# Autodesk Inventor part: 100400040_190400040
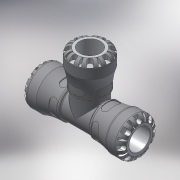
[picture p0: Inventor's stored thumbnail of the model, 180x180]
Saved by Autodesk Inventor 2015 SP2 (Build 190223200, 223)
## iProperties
Created: 2016-12
Part Number: 100400040_190400040
Material: Generic
Description: PLASSON TEE 40X40X40 SERIES 1
Document SubType Name: Modeling
Designer: KIM
Mass: 664.223 g
Surface Area: 733.008 cm^2
Volume: 474.445 cm^3
Density: 1 g/cm^3
Appearance: Default
Author: KIM
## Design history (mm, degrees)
derived "1004.ipt"
feature "Solid1::1004.ipt"
tag "TaggingFeature1"
body "Solid1"
other parameters: "d1" = 29.4, "d8" = 59.5, "d13" = 8, "d14" = 8, "d15" = 0, "d17" = 360 deg, "d19" = 8 deg, "d20" = 0.8, "d21" = 0.8, "d22" = 8 deg, "d24" = 0, "d26" = 360 deg, "d33" = 7, "d43" = 54.6, "d51" = 0.7, "d54" = 14, "d55" = 8.8, "d57" = 15.68, "d58" = 0, "d74" = 0, "d77" = 3.33333, "d79" = 54.6, "d80" = 192, "d82" = 0.8, "d115" = 360 deg, "d139" = 8, "d140" = 0, "d142" = 360 deg, "d207" = 90 deg, "d209" = 29.4, "d213" = 59.5, "d215" = 54.6, "d216" = 3.33333, "d225" = 108, "d228" = 11.9, "d229" = 8, "d233" = 8, "d234" = 0, "d236" = 360 deg, "d238" = 8 deg, "d239" = 8 deg, "d240" = 0.8, "d241" = 0.8, "d243" = 0, "d245" = 360 deg, "d247" = 1.4, "d248" = 4.2, "d249" = 4.2, "d250" = 11.9, "d252" = 14, "d253" = 9.2, "d254" = 15.68, "d255" = 0, "d257" = 360 deg, "d259" = 0.8, "d261" = 0, "d262" = 1.4, "d264" = 0, "d266" = 0, "d267" = 0.7, "A_" = 108, "H_" = 192, "d9" = 10
